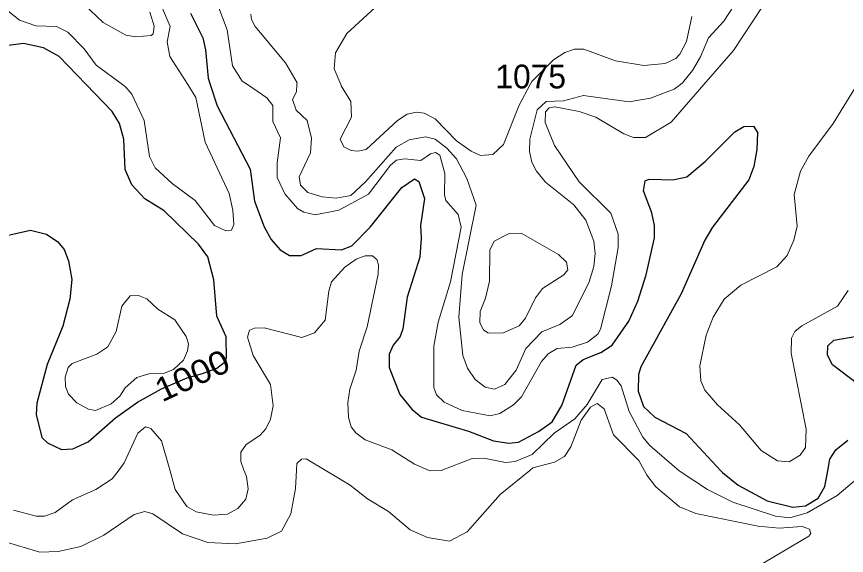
# Model space of a CAD drawing. Extents: x 473.9 to 500, y 7733.1 to 7760.8.
# Drawn here: x 476.272 to 479.07, y 7735.48 to 7737.299 of the extents above; entities that cross this region are included whole.
import ezdxf
from ezdxf.enums import TextEntityAlignment as Align

# ---------------------------------------------------------------- set-up
doc = ezdxf.new("R2010")
doc.units = 0
doc.header["$LTSCALE"] = 0.032
doc.layers.add('1', color=7, linetype='Continuous', lineweight=25)
doc.layers.add('2', color=7, linetype='Continuous', lineweight=13)
doc.layers.add('21', color=7, linetype='Continuous')
doc.layers.add('61', color=7, linetype='Continuous')

msp = doc.modelspace()

# ---------------------------------------------------------------- linework, layer by layer
at = {"layer": '1'}
for points in [[(476.858, 7737.3109), (476.9, 7737.2274), (476.9094, 7737.1863), (476.9181, 7737.0915), (476.9252, 7737.0693), (476.948, 7736.9981), (477.0592, 7736.7836), (477.0738, 7736.6759), (477.1074, 7736.589), (477.1306, 7736.5463), (477.1611, 7736.5121), (477.1923, 7736.4922), (477.232, 7736.4926), (477.283, 7736.5167), (477.3671, 7736.5121), (477.4022, 7736.5247), (477.4647, 7736.5887), (477.571, 7736.722), (477.6142, 7736.751), (477.6289, 7736.7428), (477.647, 7736.6846), (477.6335, 7736.5943), (477.6366, 7736.5508), (477.6314, 7736.4875), (477.5888, 7736.3517), (477.575, 7736.2456), (477.5656, 7736.2198), (477.5419, 7736.1896), (477.5284, 7736.1597), (477.5288, 7736.1148), (477.5639, 7736.0235), (477.6044, 7735.9745), (477.6378, 7735.9473), (477.7963, 7735.8998), (477.8802, 7735.8671), (477.9322, 7735.8593), (477.9641, 7735.8631), (478.0318, 7735.8984), (478.0781, 7735.9308), (478.1105, 7735.9859), (478.1594, 7736.1225), (478.1822, 7736.1417), (478.2425, 7736.1653), (478.2807, 7736.1897), (478.3367, 7736.2711), (478.367, 7736.3388), (478.3955, 7736.4271), (478.4232, 7736.5527), (478.4232, 7736.5937), (478.4139, 7736.6363), (478.3862, 7736.7107), (478.3919, 7736.7443), (478.4057, 7736.75), (478.4854, 7736.7479), (478.5319, 7736.7579), (478.5951, 7736.8112), (478.6945, 7736.9096), (478.7246, 7736.9284), (478.7566, 7736.9295), (478.7703, 7736.9078), (478.7687, 7736.8506), (478.7583, 7736.7927), (478.7414, 7736.7477), (478.6189, 7736.5879), (478.5924, 7736.5445), (478.5127, 7736.3628)], [(476.2287, 7736.5581), (476.3187, 7736.578), (476.3723, 7736.5646), (476.4106, 7736.5386), (476.4328, 7736.5125), (476.4466, 7736.4749), (476.4579, 7736.4112), (476.4515, 7736.345), (476.4282, 7736.254), (476.3745, 7736.1253), (476.3406, 7735.9945), (476.3375, 7735.9565), (476.3572, 7735.8789), (476.3765, 7735.8601), (476.4232, 7735.8376), (476.4615, 7735.8399), (476.5133, 7735.864), (476.6051, 7735.9445), (476.6792, 7735.998), (476.7607, 7736.0422), (476.8474, 7736.0799), (476.8991, 7736.0945), (476.9473, 7736.1129), (476.9723, 7736.1312), (476.9798, 7736.1458), (476.979, 7736.2186), (476.9469, 7736.288), (476.9366, 7736.4103), (476.9171, 7736.4885), (476.8851, 7736.5303), (476.7691, 7736.6431), (476.7039, 7736.6842), (476.6603, 7736.731), (476.6383, 7736.7825), (476.6333, 7736.8853), (476.6193, 7736.938), (476.5943, 7736.978), (476.5064, 7737.0693), (476.4154, 7737.1637), (476.3631, 7737.1938), (476.2952, 7737.2076), (476.2181, 7737.1978)], [(478.5127, 7736.3628), (478.3766, 7736.1165), (478.3693, 7736.0908), (478.3683, 7736.0344), (478.3862, 7735.9834), (478.4242, 7735.9468), (478.53, 7735.8921), (478.647, 7735.766), (478.652, 7735.7606), (478.7055, 7735.7173), (478.8031, 7735.6644), (478.8898, 7735.6431), (478.9326, 7735.6477), (478.9746, 7735.6735), (478.9977, 7735.7127), (479.0072, 7735.7655), (479.0145, 7735.8056), (479.0342, 7735.8372), (479.0748, 7735.8698)], [(479.1355, 7736.0379), (479.0238, 7736.1241), (479.0063, 7736.1568), (479.0074, 7736.1883), (479.0279, 7736.2065), (479.1319, 7736.2254)]]:
    msp.add_lwpolyline(points, dxfattribs=at)
at = {"layer": '2'}
for points in [[(476.7208, 7737.3138), (476.7354, 7737.2665), (476.7328, 7737.2411), (476.7262, 7737.2353), (476.6746, 7737.2308), (476.6408, 7737.2363), (476.5636, 7737.2785), (476.4566, 7737.3812)], [(478.5488, 7737.2991), (478.5316, 7737.2151), (478.509, 7737.1715), (478.4952, 7737.1571), (478.4595, 7737.1407), (478.3876, 7737.1336), (478.2918, 7737.1495), (478.185, 7737.189), (478.1529, 7737.189), (478.1208, 7737.1778), (478.0822, 7737.1528), (478.0095, 7737.08), (478.0037, 7737.0693), (477.9664, 7737.0001), (477.9143, 7736.8672), (477.8779, 7736.8337), (477.8366, 7736.8298), (477.805, 7736.8444), (477.7558, 7736.8796), (477.6834, 7736.9534), (477.646, 7736.9733), (477.6206, 7736.976), (477.5896, 7736.9692), (477.5568, 7736.9481), (477.4506, 7736.8506), (477.4223, 7736.8442), (477.4008, 7736.8469), (477.3753, 7736.8595), (477.3629, 7736.8855), (477.4013, 7736.9599), (477.3989, 7737.0127), (477.3668, 7737.0655), (477.3652, 7737.0693), (477.3425, 7737.1228), (477.3469, 7737.176), (477.3859, 7737.2413), (477.5095, 7737.3564)], [(476.2121, 7737.3418), (476.2814, 7737.2867), (476.3363, 7737.2676), (476.4066, 7737.2654), (476.4451, 7737.2467), (476.4996, 7737.1895), (476.5405, 7737.1349), (476.6287, 7737.0693), (476.6406, 7737.0604), (476.6601, 7737.0366), (476.7018, 7736.9481), (476.7201, 7736.827), (476.7387, 7736.7879), (476.7961, 7736.7355), (476.8737, 7736.6777), (476.9389, 7736.5942), (476.978, 7736.5757), (476.9962, 7736.5784), (477.0047, 7736.5976), (477.0016, 7736.6458), (476.9888, 7736.702), (476.9083, 7736.8747), (476.8768, 7737.0259), (476.8492, 7737.0693), (476.789, 7737.1638), (476.7797, 7737.214), (476.7894, 7737.2657), (476.7605, 7737.3341)], [(476.9501, 7737.3373), (476.9826, 7737.2544), (476.9998, 7737.1325), (477.033, 7737.0814), (477.0506, 7737.0693), (477.1153, 7737.0246), (477.1358, 7736.9985), (477.1359, 7736.9448), (477.1624, 7736.8894), (477.1504, 7736.8055), (477.1511, 7736.7563), (477.177, 7736.7004), (477.2195, 7736.6513), (477.2406, 7736.6388), (477.2787, 7736.6303), (477.3591, 7736.6452)], [(477.062, 7737.3072), (477.0638, 7737.2885), (477.0767, 7737.265), (477.1784, 7737.1432), (477.2177, 7737.0754), (477.2174, 7737.0693), (477.2163, 7737.0453), (477.2026, 7737.0189), (477.2147, 7736.9834), (477.2522, 7736.9478), (477.2669, 7736.8886), (477.2626, 7736.8388), (477.2251, 7736.7584), (477.2295, 7736.7294), (477.2538, 7736.7051), (477.3027, 7736.6905), (477.3495, 7736.6866), (477.3996, 7736.6951), (477.4486, 7736.7413), (477.5523, 7736.8579), (477.5963, 7736.883), (477.6507, 7736.8932), (477.6838, 7736.8848), (477.7227, 7736.8553), (477.7549, 7736.8184), (477.7905, 7736.7524), (477.8216, 7736.6624), (477.7749, 7736.4281), (477.763, 7736.2845), (477.7769, 7736.1546), (477.7927, 7736.1124), (477.818, 7736.0743), (477.8521, 7736.0483), (477.8832, 7736.0411), (477.9183, 7736.0569), (477.9562, 7736.1051), (477.9897, 7736.1784), (478.0427, 7736.2346), (478.1035, 7736.2599), (478.1472, 7736.2902), (478.2031, 7736.4042), (478.2186, 7736.456), (478.2229, 7736.499), (478.2181, 7736.5413), (478.1914, 7736.6117), (478.1512, 7736.6633), (478.056, 7736.7402), (478.0258, 7736.7769), (478.0098, 7736.8081), (478.0018, 7736.8438), (478.0024, 7736.8848), (478.0278, 7736.9845), (478.0577, 7737.0118), (478.1158, 7737.0147), (478.1835, 7737.033), (478.3373, 7737.0114), (478.4092, 7737.0232), (478.49, 7737.0535), (478.5105, 7737.0693), (478.5179, 7737.075), (478.5512, 7737.1164), (478.5786, 7737.1632), (478.6048, 7737.2268), (478.6565, 7737.2837), (478.6906, 7737.335)], [(477.3591, 7736.6452), (477.4583, 7736.6992), (477.5326, 7736.7979), (477.5534, 7736.814), (477.5804, 7736.8193), (477.6355, 7736.8133), (477.6681, 7736.8356), (477.6849, 7736.8398), (477.6987, 7736.8307), (477.7162, 7736.7691), (477.7149, 7736.6977), (477.7198, 7736.6783), (477.7612, 7736.631), (477.771, 7736.5884), (477.7356, 7736.4036), (477.6941, 7736.2679), (477.6786, 7736.1864), (477.6789, 7736.047), (477.688, 7736.0223), (477.7135, 7735.9971), (477.7745, 7735.9697), (477.8694, 7735.9517), (477.9014, 7735.9594), (477.9482, 7735.9891), (477.9752, 7736.0152), (478.0424, 7736.1351), (478.0645, 7736.1607), (478.0945, 7736.1782), (478.1459, 7736.1836), (478.1975, 7736.2002), (478.2316, 7736.2275), (478.2409, 7736.2438), (478.2783, 7736.3907), (478.3009, 7736.5199), (478.3012, 7736.5643), (478.2758, 7736.6351), (478.1694, 7736.7408), (478.0858, 7736.8633), (478.054, 7736.9412), (478.0555, 7736.9779), (478.0679, 7736.9907), (478.0869, 7736.9945), (478.169, 7736.9784), (478.2252, 7736.9591), (478.3193, 7736.9033), (478.3523, 7736.8912), (478.3931, 7736.8913), (478.4792, 7736.943), (478.5892, 7737.0693), (478.6897, 7737.1846), (478.7869, 7737.3324)], [(479.1069, 7737.0693), (479.0253, 7736.9381), (478.9442, 7736.8279), (478.9155, 7736.7772), (478.8943, 7736.699), (478.9046, 7736.5916), (478.8936, 7736.5439), (478.871, 7736.4926), (478.8362, 7736.4543), (478.7142, 7736.393), (478.6584, 7736.3453), (478.6205, 7736.284), (478.5978, 7736.2239), (478.5759, 7736.12), (478.5796, 7736.0701), (478.5931, 7736.038), (478.6357, 7735.9882), (478.7101, 7735.9211), (478.7828, 7735.8348), (478.8385, 7735.7994), (478.8768, 7735.7958), (478.9142, 7735.8191), (478.9326, 7735.8451), (478.9345, 7735.9061), (478.8836, 7736.1627), (478.8856, 7736.2132), (478.8963, 7736.2358), (478.9199, 7736.2556), (479.0405, 7736.3215), (479.0767, 7736.3747)], [(477.8088, 7735.8077), (477.704, 7735.7675), (477.7037, 7735.7674), (477.668, 7735.7657), (477.6636, 7735.7676), (477.6143, 7735.7885), (477.5369, 7735.8368), (477.4474, 7735.871), (477.4158, 7735.8946), (477.4007, 7735.9142), (477.3914, 7735.9463), (477.3891, 7735.9964), (477.3962, 7736.0412), (477.4172, 7736.1061), (477.4267, 7736.1698), (477.454, 7736.2518), (477.4913, 7736.4298), (477.4928, 7736.4615), (477.487, 7736.4791), (477.4726, 7736.4917), (477.447, 7736.4911), (477.4176, 7736.4804), (477.3785, 7736.4534), (477.334, 7736.404), (477.3246, 7736.3726), (477.3125, 7736.2744), (477.277, 7736.2311), (477.2342, 7736.2163), (477.1066, 7736.2482), (477.0745, 7736.2476), (477.057, 7736.2405), (477.0507, 7736.217), (477.0702, 7736.1554), (477.1279, 7736.0573), (477.1374, 7735.9849), (477.1286, 7735.9398), (477.1127, 7735.9075), (477.0922, 7735.8855), (477.0461, 7735.8547), (477.0283, 7735.8287), (477.0277, 7735.7974), (477.0387, 7735.7686), (477.0472, 7735.7464), (477.053, 7735.7051), (477.0449, 7735.6702), (477.0186, 7735.6389), (476.9828, 7735.6202), (476.9362, 7735.6165), (476.8778, 7735.628), (476.8457, 7735.6456), (476.807, 7735.7026), (476.7884, 7735.769), (476.7608, 7735.8671), (476.7248, 7735.9092), (476.7061, 7735.9139), (476.6809, 7735.8933), (476.6352, 7735.7932), (476.6174, 7735.7692), (476.5945, 7735.7385), (476.5393, 7735.7029), (476.4605, 7735.6681), (476.4021, 7735.6252), (476.3662, 7735.6135), (476.3385, 7735.6124), (476.262, 7735.6333)], [(479.1117, 7735.7438), (479.039, 7735.6822), (478.9382, 7735.6239), (478.8798, 7735.6069), (478.831, 7735.6134), (478.6873, 7735.6604), (478.6018, 7735.7024), (478.5092, 7735.7639), (478.5065, 7735.7662), (478.4071, 7735.8519), (478.384, 7735.8797), (478.3373, 7735.9661), (478.3106, 7736.0528), (478.2967, 7736.0724), (478.2814, 7736.0819), (478.2465, 7736.0739), (478.196, 7735.9898), (478.1541, 7735.9417), (478.0849, 7735.8934), (478.0107, 7735.8213), (477.953, 7735.7972), (477.9203, 7735.7942), (477.8474, 7735.8087), (477.8088, 7735.8077)], [(476.2302, 7735.5278), (476.3505, 7735.4914), (476.4116, 7735.4939), (476.4884, 7735.5103), (476.5666, 7735.5483), (476.6685, 7735.619), (476.7047, 7735.6291), (476.7314, 7735.6204), (476.8313, 7735.5535), (476.9174, 7735.5241), (477.0101, 7735.5192), (477.1173, 7735.5385), (477.1648, 7735.5621), (477.197, 7735.6209), (477.2124, 7735.7066), (477.2161, 7735.7683), (477.2175, 7735.7907), (477.2323, 7735.8052), (477.2489, 7735.8064), (477.3127, 7735.7681), (477.3964, 7735.7179), (477.4553, 7735.6712), (477.5257, 7735.6284), (477.599, 7735.5666), (477.6572, 7735.541), (477.7318, 7735.5291), (477.7915, 7735.5597), (477.9032, 7735.6859), (478.0025, 7735.767), (478.013, 7735.7756), (478.086, 7735.7957), (478.1202, 7735.8147), (478.1406, 7735.8467), (478.1763, 7735.9372), (478.2076, 7735.9806), (478.23, 7735.9933), (478.2537, 7735.9752), (478.2847, 7735.8874), (478.3699, 7735.8013), (478.389, 7735.7664), (478.3971, 7735.7516), (478.4282, 7735.7118), (478.508, 7735.645), (478.5625, 7735.6222), (478.7725, 7735.5795), (478.8432, 7735.573), (478.9215, 7735.5778)], [(478.9215, 7735.5778), (478.9457, 7735.5686), (478.9505, 7735.5542), (478.9435, 7735.5452), (478.7671, 7735.4403)]]:
    msp.add_lwpolyline(points, dxfattribs=at)
for points in [[(477.9108, 7736.2307), (477.9664, 7736.2548), (477.988, 7736.2806), (478.0221, 7736.3494), (478.046, 7736.3817), (478.1175, 7736.4269), (478.1312, 7736.4438), (478.1268, 7736.4703), (478.0995, 7736.4964), (477.9739, 7736.5676), (477.9326, 7736.5667), (477.8825, 7736.5412), (477.8674, 7736.5107), (477.8666, 7736.4059), (477.8533, 7736.3483), (477.8352, 7736.3033), (477.8343, 7736.2657), (477.8463, 7736.2421), (477.8608, 7736.2321)], [(476.6196, 7736.0178), (476.6381, 7736.0457), (476.6773, 7736.0809), (476.718, 7736.093), (476.7705, 7736.0958), (476.801, 7736.1075), (476.8352, 7736.1394), (476.8488, 7736.1708), (476.8512, 7736.1941), (476.8441, 7736.2198), (476.8053, 7736.2757), (476.748, 7736.3111), (476.7117, 7736.3464), (476.6826, 7736.3573), (476.6544, 7736.3567), (476.6268, 7736.3211), (476.6081, 7736.2359), (476.5794, 7736.1849), (476.5428, 7736.1591), (476.4594, 7736.1284), (476.446, 7736.1143), (476.4361, 7736.0821), (476.4365, 7736.0506), (476.447, 7736.025), (476.4755, 7735.9959), (476.5148, 7735.9741), (476.5377, 7735.9693), (476.5912, 7735.9918)]]:
    msp.add_lwpolyline(points, close=True, dxfattribs=at)

# ---------------------------------------------------------------- texts
at = {"layer": '21'}
msp.add_text('1075', height=0.08, dxfattribs=at).set_placement((477.8867, 7737.0566))
at = {"layer": '61', "width": 1.1}
msp.add_text('1000', height=0.08, rotation=24.948, dxfattribs=at).set_placement((476.8811, 7736.0515), align=Align.CENTER)

doc.saveas('drawing.dxf')
